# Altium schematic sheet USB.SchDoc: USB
size A4; Author: Daniela Catanzaro; CompanyName: Arduino srl; DocumentNumber: ASX00055; SheetNumber: 7; SheetTotal: 10; RevAuthor: Daniela Catanzaro
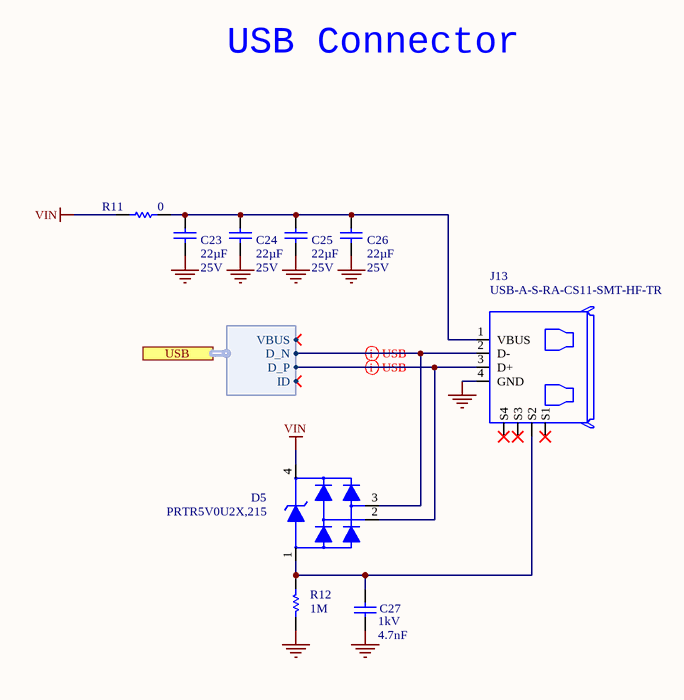
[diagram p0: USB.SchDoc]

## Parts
C23  value 22µF  Voltage: 25V  [CAP-0805]  (hidden comment: CL21A226MAQNNNE)
C24  value 22µF  Voltage: 25V  [CAP-0805]  (hidden comment: CL21A226MAQNNNE)
C25  value 22µF  Voltage: 25V  [CAP-0805]  (hidden comment: CL21A226MAQNNNE)
C26  value 22µF  Voltage: 25V  [CAP-0805]  (hidden comment: CL21A226MAQNNNE)
C27  value 4.7nF  Voltage: 1kV  [CAP-0805]  (hidden comment: FV21X472K102ECG)
D5  PRTR5V0U2X,215  [SOT190P230X110-4N]
J13  USB-A-S-RA-CS11-SMT-HF-TR  [USB-A-S-RA-CS11-SMT-HF-TR]
R11  value 0  [RES-0603]  (hidden comment: CRCW06030000Z0EAC)
R12  value 1M  [RES-0603]  (hidden comment: CRCW06031M00FKEA)

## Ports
USB (harness USB)

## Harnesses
USB: VBUS, D_P, D_N, ID

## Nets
GND: C23.1 C24.1 C25.1 C26.1 C27.1 J13.4(GND) R12.1
VIN: D5.4 R11.1
NetC23_2: C23.2 C24.2 C25.2 C26.2 J13.1(VBUS) R11.2
NetC27_2: C27.2 D5.1 J13.SHIELD2(S2) R12.2
NetD5_2: D5.2 J13.3(D+) ; port USB.D_P
NetD5_3: D5.3 J13.2(D-) ; port USB.D_N

Not connected (* = marked no-connect by the designer): J13 SHIELD1(S1)* SHIELD3(S3)* SHIELD4(S4)*

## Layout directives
differential pair; differential pair class USB; net class DIFFERENTIAL: NetD5_2, NetD5_3

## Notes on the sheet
- USB Connector

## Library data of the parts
C23-C26 = C0111-A.7: CAP CHIP 0805 22uF 20% 25V X5R; Manufacturer: Samsung Electro-Mechanics; Code Arduino: C0111
C27 = C0059-A.14: CAP CHIP 0805 4.7nF 10% 1000V X7R; Manufacturer: PSA Shenzen; Code Arduino: 0689
D5 = D0025-A.5: TVS ARRAY 4LIN.8kV 1pF SOT143B; Manufacturer: Nexperia; Device Type: ESD protection; Code Arduino: 2209
J13 = J0329-A.9: CONN USB A 2.0 FEMALE RIGHT ANGLE SMD + TH TAPE AND REEL; Manufacturer: Adam Tech; Code Arduino: J0329
R11 = R0096-A.22: RES CHIP 0603 0R 1/10W; Manufacturer: Vishay; Code Arduino: 0233; Tolerance: 0%; Power: 100mW; Temperature coefficient: 0ppm
R12 = R0163-A.20: RES CHIP 0603 1M 1% 1/10W; Manufacturer: Vishay; Power: 100mW; Code Arduino: R0163; Temperature coefficient: 100ppm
